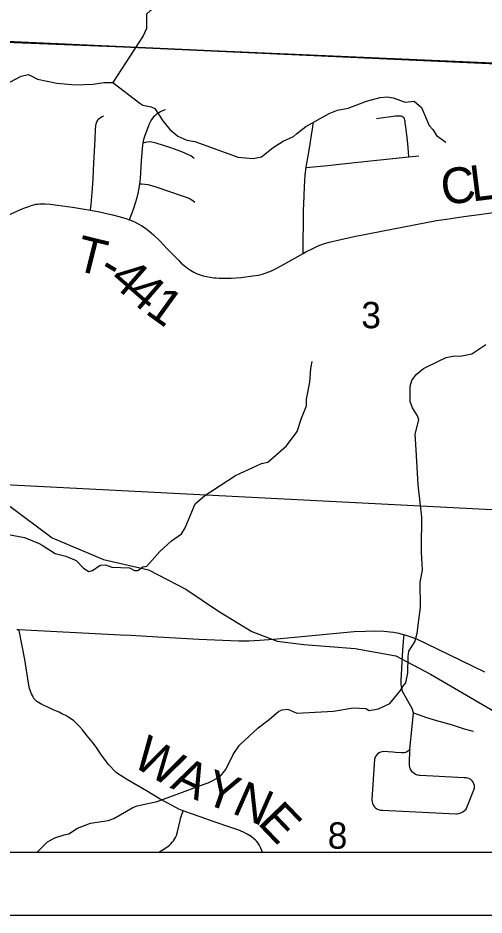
# Model space of a CAD drawing. Extents: x 0 to 34, y 0 to 22.
# Drawn here: x 2.723 to 3.463, y 14 to 15.425 of the extents above; entities that cross this region are included whole.
import ezdxf

# ---------------------------------------------------------------- set-up
doc = ezdxf.new("R2010")
doc.units = 0
for name, color, linetype in [('GM_X_County_Road', 7, 'Continuous'), ('GM_X_County_Road_Text', 7, 'Continuous'), ('GM_X_Minor_River', 7, 'Continuous'), ('GM_X_Rail_Line', 7, 'Continuous'), ('GM_X_Section', 7, 'Continuous'), ('GM_X_Section_Text', 7, 'Continuous'), ('GM_X_State_Route', 7, 'Continuous'), ('GM_X_Township_Road', 7, 'Continuous'), ('GM_X_Township_Road_Text', 7, 'Continuous'), ('GM_X_Unincorporated_Text', 7, 'Continuous'), ('SH_Data', 7, 'Continuous')]:
    doc.layers.add(name, color=color, linetype=linetype)

msp = doc.modelspace()

# ---------------------------------------------------------------- linework, layer by layer
at = {"layer": 'GM_X_County_Road'}
for points in [[(2.7863, 14.3229), (2.7788, 14.3262), (2.7699, 14.3301), (2.7606, 14.3344), (2.7579, 14.3359), (2.7552, 14.3374), (2.7525, 14.3393), (2.7504, 14.3413), (2.7479, 14.344), (2.7469, 14.3459), (2.7456, 14.3487), (2.7443, 14.3513), (2.7431, 14.3541), (2.7412, 14.3598), (2.7405, 14.3627), (2.7395, 14.3682), (2.7334, 14.4058), (2.725, 14.4495), (2.7243, 14.4533)], [(2.9851, 14.1655), (2.9837, 14.166), (2.978, 14.1683), (2.9676, 14.1738), (2.9486, 14.1843), (2.9269, 14.1972), (2.8967, 14.2149), (2.8866, 14.221), (2.8825, 14.2236), (2.8788, 14.2266), (2.8743, 14.2306), (2.87, 14.2352), (2.8661, 14.2396), (2.8607, 14.2468), (2.8571, 14.2517), (2.8535, 14.2572), (2.8474, 14.2659), (2.8403, 14.2752), (2.8327, 14.2847), (2.825, 14.294), (2.8204, 14.2994), (2.8159, 14.3041), (2.8115, 14.3084), (2.8063, 14.3124), (2.8021, 14.315), (2.7989, 14.3167), (2.7937, 14.3193), (2.7882, 14.3221), (2.7863, 14.3229)], [(3.1108, 14.1), (3.1085, 14.106), (3.1058, 14.1116), (3.1041, 14.1142), (3.1021, 14.1167), (3.0999, 14.119), (3.0969, 14.1216), (3.0928, 14.1246), (3.0866, 14.1286), (3.0807, 14.1314), (3.0734, 14.1346), (3.0593, 14.1396), (3.0342, 14.1483), (3.0135, 14.1554), (2.9968, 14.1611), (2.9851, 14.1655)]]:
    msp.add_lwpolyline(points, dxfattribs=at)
at = {"layer": 'GM_X_Minor_River'}
for points in [[(3.0044, 15.5355), (2.9817, 15.4934), (2.9603, 15.4728), (2.955, 15.4693), (2.9332, 15.4369), (2.9268, 15.4312), (2.927, 15.408), (2.9213, 15.3966), (2.8733, 15.3227)], [(2.6921, 15.3141), (2.728, 15.3325), (2.7389, 15.3352), (2.745, 15.3326), (2.7537, 15.3277), (2.7844, 15.3214), (2.8136, 15.3186), (2.8423, 15.3198), (2.8589, 15.3226), (2.8733, 15.3227), (2.9162, 15.2895), (2.9212, 15.2865), (2.9344, 15.2839), (2.9401, 15.2809), (2.9527, 15.2616)], [(2.9527, 15.2616), (2.9641, 15.2476), (2.9766, 15.2374), (2.9907, 15.2307), (3.0035, 15.2288), (3.0574, 15.2094), (3.0634, 15.2071), (3.0721, 15.2041), (3.0964, 15.2016), (3.1092, 15.2043), (3.128, 15.2192), (3.1439, 15.2292), (3.1601, 15.2365), (3.165, 15.2407), (3.1797, 15.2526), (3.2167, 15.2733), (3.2303, 15.2787), (3.2469, 15.2818), (3.2759, 15.2929), (3.2979, 15.2988), (3.3092, 15.2996), (3.3187, 15.2981), (3.3376, 15.2914), (3.352, 15.2926), (3.3634, 15.2828), (3.3756, 15.2544), (3.3813, 15.2476), (3.3871, 15.2385), (3.4023, 15.2279)], [(2.7531, 14.1), (2.7694, 14.1165), (2.7811, 14.1227), (2.7962, 14.1273), (2.8034, 14.1289), (2.8174, 14.1381), (2.8381, 14.1461), (2.8661, 14.1501), (2.8748, 14.1536), (2.9053, 14.1708), (2.9121, 14.1735), (2.9439, 14.1801), (3.0183, 14.2079), (3.025, 14.2102), (3.0435, 14.2194), (3.0526, 14.2312), (3.0642, 14.2552), (3.0747, 14.2697), (3.104, 14.2972), (3.1218, 14.3106), (3.1368, 14.3239), (3.1425, 14.3262), (3.1512, 14.3271), (3.1656, 14.3207), (3.2238, 14.3237), (3.2552, 14.3291), (3.2752, 14.3281), (3.2802, 14.3251), (3.2953, 14.3275), (3.313, 14.3359), (3.3303, 14.3569), (3.3337, 14.363), (3.3386, 14.3691), (3.3419, 14.3847), (3.3421, 14.4109), (3.3436, 14.4192), (3.353, 14.4341), (3.3567, 14.447), (3.3589, 14.4649), (3.3618, 14.4884), (3.3616, 14.529), (3.3649, 14.5477), (3.3636, 14.5765), (3.3636, 14.583), (3.3641, 14.632), (3.3582, 14.6836), (3.3552, 14.739), (3.3532, 14.7637), (3.3591, 14.7865), (3.3572, 14.7929), (3.3492, 14.8058), (3.3454, 14.8156), (3.3456, 14.8399), (3.3482, 14.8491), (3.355, 14.8586), (3.3667, 14.8682), (3.3916, 14.8804), (3.4025, 14.8854), (3.4161, 14.8882), (3.4248, 14.8878), (3.4433, 14.8917), (3.4656, 14.9063)], [(2.7989, 14.57), (2.8152, 14.5629), (2.827, 14.5508), (2.835, 14.5455), (2.841, 14.5475), (2.8531, 14.5555), (2.8618, 14.5563), (2.872, 14.5526), (2.9, 14.5516), (2.908, 14.5475), (2.9132, 14.5471), (2.9212, 14.5529), (2.9276, 14.5544), (2.9479, 14.5777), (2.9667, 14.5945), (2.9716, 14.5979), (2.9822, 14.6056), (2.9882, 14.6151), (3.0042, 14.6532), (3.0197, 14.6665), (3.0683, 14.6983), (3.1095, 14.7175), (3.1193, 14.7195), (3.149, 14.7455), (3.1663, 14.7683), (3.173, 14.7893), (3.1809, 14.809), (3.1808, 14.8193), (3.1863, 14.8463), (3.1877, 14.8683), (3.1899, 14.8793)], [(2.6992, 14.6063), (2.7333, 14.5997), (2.7564, 14.5903), (2.7614, 14.5873), (2.7818, 14.5741), (2.7989, 14.57)]]:
    msp.add_lwpolyline(points, dxfattribs=at)
at = {"layer": 'GM_X_Rail_Line'}
for points in [[(2.1, 18.4819), (2.1, 15.4153), (3.9123, 15.3323), (3.9451, 15.3313), (3.973, 15.329), (4.0133, 15.3262), (4.0257, 15.3251), (4.0381, 15.324), (4.0782, 15.3206), (4.1061, 15.3185), (4.1743, 15.3141), (4.1849, 15.3132), (4.1956, 15.3121), (4.1973, 15.3118), (5.1044, 15.2759), (5.2458, 15.271), (5.4522, 15.2638), (5.479, 15.731), (5.4821, 15.8189)], [(2.7058, 14.6525), (2.777, 14.599), (2.8584, 14.5647), (2.9302, 14.5482), (2.9894, 14.5175), (3.0412, 14.4829), (3.0941, 14.4502), (3.1342, 14.4352), (3.1768, 14.4296), (3.258, 14.4232), (3.3229, 14.4116), (3.3777, 14.3824), (3.5429, 14.2865)]]:
    msp.add_lwpolyline(points, dxfattribs=at)
msp.add_lwpolyline([(2.1, 15.4153), (2.1, 14.1), (6.4223, 14.1), (6.4607, 14.8895), (6.4764, 15.22), (6.2705, 15.2288), (5.4522, 15.2638), (5.2458, 15.271), (5.1044, 15.2759), (4.1973, 15.3118), (4.1956, 15.3121), (4.1849, 15.3132), (4.1743, 15.3141), (4.1061, 15.3185), (4.0782, 15.3206), (4.0381, 15.324), (4.0257, 15.3251), (4.0133, 15.3262), (3.973, 15.329), (3.9451, 15.3313), (3.9123, 15.3323)], close=True, dxfattribs=at)
at = {"layer": 'GM_X_Section'}
msp.add_lwpolyline([(2.9571, 15.3766), (3.7314, 15.3424), (3.7021, 14.6318), (2.6704, 14.6848), (2.7035, 15.3864)], close=True, dxfattribs=at)
at = {"layer": 'GM_X_State_Route'}
for points in [[(2.7211, 14.4534), (2.7243, 14.4533), (2.8855, 14.4452)], [(2.8855, 14.4452), (2.9015, 14.4444), (2.9449, 14.4418), (3.0098, 14.4381), (3.0736, 14.4356), (3.0895, 14.4356), (3.1062, 14.4364), (3.1286, 14.4381), (3.1617, 14.4413), (3.2567, 14.4502), (3.2747, 14.451), (3.2885, 14.4515), (3.3039, 14.451), (3.319, 14.4494), (3.3276, 14.4475), (3.3358, 14.4453), (3.3368, 14.4451), (3.3449, 14.4426), (3.3557, 14.4386), (3.3886, 14.423), (3.4633, 14.3863)]]:
    msp.add_lwpolyline(points, dxfattribs=at)
at = {"layer": 'GM_X_Township_Road'}
msp.add_line((3.3434, 15.2043), (3.359, 15.2059), dxfattribs=at)
for points in [[(2.9216, 15.2268), (2.9227, 15.2318), (2.9237, 15.2355), (2.9249, 15.2388), (2.9279, 15.2469), (2.9312, 15.2555), (2.9326, 15.2588), (2.9341, 15.2619), (2.9354, 15.2639), (2.9373, 15.2664), (2.9392, 15.2688), (2.9415, 15.2711), (2.9438, 15.273), (2.9462, 15.2747), (2.9493, 15.2765), (2.9529, 15.2781), (2.957, 15.2795)], [(2.838, 15.1195), (2.8389, 15.1284), (2.8402, 15.1415), (2.8411, 15.154), (2.842, 15.1696), (2.8432, 15.1946), (2.8451, 15.232), (2.8458, 15.2476), (2.8464, 15.2537), (2.847, 15.2568), (2.8479, 15.2598), (2.8493, 15.2625), (2.8513, 15.2649), (2.8536, 15.2669), (2.8563, 15.2685), (2.8592, 15.2695)], [(3.292, 15.2652), (3.3221, 15.2694), (3.3282, 15.2697), (3.3298, 15.2696), (3.3312, 15.2693), (3.3323, 15.269), (3.333, 15.2687), (3.3335, 15.2684), (3.3341, 15.268), (3.3347, 15.2674)], [(3.3434, 15.2043), (3.3425, 15.219), (3.3412, 15.2301), (3.3385, 15.2521), (3.3378, 15.2581), (3.3373, 15.2611), (3.3369, 15.2628), (3.3363, 15.2646), (3.336, 15.2655), (3.3357, 15.2661), (3.3353, 15.2668), (3.3347, 15.2674)], [(3.1803, 15.1873), (3.1808, 15.1909), (3.1833, 15.2061), (3.186, 15.2213), (3.1901, 15.2456), (3.1911, 15.2517), (3.1917, 15.2577)], [(2.9164, 15.1613), (2.9172, 15.1702), (2.9191, 15.1981), (2.9205, 15.2174), (2.921, 15.2226), (2.9216, 15.2268)], [(2.9216, 15.2268), (2.9251, 15.2277), (2.928, 15.2283), (2.9312, 15.2285), (2.9354, 15.2281), (2.9418, 15.2265), (2.9648, 15.219), (2.9823, 15.2128), (2.9943, 15.2078), (2.9974, 15.2063), (2.9999, 15.2045), (3.0025, 15.2021)], [(3.1803, 15.1873), (3.2148, 15.1907), (3.2382, 15.1932), (3.2722, 15.197), (3.2978, 15.1997), (3.3434, 15.2043)], [(3.1754, 15.0509), (3.1762, 15.1186), (3.177, 15.1425), (3.1776, 15.1573), (3.178, 15.1661), (3.1789, 15.1757), (3.1803, 15.1873)], [(2.8996, 15.1043), (2.9009, 15.1075), (2.9039, 15.1155), (2.9073, 15.1245), (2.9095, 15.1313), (2.9119, 15.1398), (2.9142, 15.1488), (2.9159, 15.1579), (2.9164, 15.1613)], [(2.9164, 15.1613), (2.9196, 15.1613), (2.924, 15.161), (2.9287, 15.1604), (2.9347, 15.1591), (2.9448, 15.1557), (2.9816, 15.1432), (2.9932, 15.139), (2.9964, 15.1375), (2.9987, 15.1363), (3.0011, 15.1344), (3.0035, 15.1324)], [(2.5577, 15.0512), (2.5773, 15.0578), (2.5878, 15.0617), (2.5976, 15.0656), (2.6721, 15.0956), (2.6861, 15.1016), (2.6982, 15.1073), (2.7259, 15.12), (2.732, 15.1227), (2.7399, 15.1257), (2.7452, 15.1275), (2.7478, 15.1282), (2.7509, 15.129), (2.754, 15.1294), (2.7569, 15.1296), (2.7593, 15.1296), (2.7659, 15.1295), (2.774, 15.129), (2.7856, 15.1276), (2.8092, 15.1244), (2.8317, 15.1207), (2.838, 15.1195)], [(3.1754, 15.0509), (3.1797, 15.0533), (3.1907, 15.059), (3.1993, 15.0629), (3.2081, 15.0662), (3.2171, 15.0689), (3.2352, 15.0733), (3.2566, 15.0776), (3.3002, 15.0864), (3.3873, 15.103), (3.403, 15.1051), (3.4306, 15.1094), (3.4552, 15.113), (3.486, 15.1172), (3.5015, 15.1188), (3.5201, 15.1201), (3.5543, 15.1218), (3.5729, 15.1225), (3.5885, 15.1224), (3.6017, 15.1219)], [(2.838, 15.1195), (2.8521, 15.117), (2.8729, 15.1124), (2.8849, 15.1092), (2.8939, 15.1065), (2.8996, 15.1043)], [(2.8996, 15.1043), (2.9039, 15.1026), (2.9088, 15.1005), (2.9137, 15.0981), (2.9192, 15.095), (2.9252, 15.0911), (2.9306, 15.087), (2.9379, 15.0804), (2.9478, 15.0709), (2.9598, 15.0584), (2.9779, 15.0396), (2.9821, 15.0354), (2.9864, 15.0316), (2.9917, 15.0277), (2.9966, 15.0242), (3.0019, 15.0213), (3.0073, 15.0187), (3.0122, 15.0169), (3.0168, 15.0154), (3.0222, 15.0142), (3.0278, 15.0132), (3.0337, 15.0124), (3.0377, 15.012), (3.0423, 15.0119), (3.0522, 15.0118), (3.0613, 15.0119), (3.0773, 15.0129), (3.0958, 15.0151), (3.1049, 15.0166), (3.1109, 15.018), (3.1168, 15.0199), (3.1253, 15.0234), (3.1337, 15.0274), (3.1446, 15.0333), (3.1754, 15.0509)], [(3.3449, 14.2633), (3.3448, 14.263), (3.3431, 14.2611), (3.3411, 14.2595), (3.3388, 14.2584), (3.3364, 14.2578), (3.3338, 14.2576), (3.3323, 14.2578), (3.3224, 14.2584), (3.3177, 14.2587), (3.3034, 14.2595), (3.3011, 14.2594), (3.2985, 14.2587), (3.296, 14.2576), (3.2938, 14.2561), (3.292, 14.2541), (3.2905, 14.2518), (3.2895, 14.2493), (3.2891, 14.2476), (3.2847, 14.1836), (3.2847, 14.1829), (3.2849, 14.1801), (3.2856, 14.1773), (3.2869, 14.1748), (3.2885, 14.1724), (3.2905, 14.1704), (3.2928, 14.1688), (3.2954, 14.1676), (3.2982, 14.1668), (3.301, 14.1666), (3.3017, 14.1666), (3.4178, 14.1608), (3.4192, 14.1609), (3.4226, 14.1614), (3.4259, 14.1624), (3.429, 14.1639), (3.4318, 14.1658), (3.4343, 14.1682), (3.4344, 14.1683), (3.4477, 14.2016), (3.4478, 14.2032), (3.4475, 14.2059), (3.4468, 14.2086), (3.4456, 14.211), (3.4439, 14.2132), (3.4419, 14.2151), (3.4395, 14.2165), (3.437, 14.2175), (3.4343, 14.218), (3.4315, 14.218), (3.4314, 14.218), (3.3616, 14.2214), (3.3598, 14.2215), (3.3569, 14.2221), (3.3541, 14.2233), (3.3516, 14.2248), (3.3494, 14.2267), (3.3476, 14.229), (3.3461, 14.2316), (3.3451, 14.2344), (3.3446, 14.2373), (3.3446, 14.2394), (3.3449, 14.2633), (3.3487, 14.2994), (3.351, 14.3211), (3.3487, 14.3279), (3.3333, 14.3552), (3.3328, 14.3581), (3.3322, 14.3598), (3.3316, 14.3628), (3.3314, 14.3662), (3.3312, 14.3724), (3.3322, 14.3911), (3.3335, 14.4129), (3.3349, 14.4347), (3.3354, 14.441), (3.3358, 14.4453)], [(3.351, 14.3211), (3.3564, 14.319), (3.358, 14.3183), (3.3713, 14.3139), (3.3872, 14.3092), (3.4106, 14.3024), (3.4314, 14.296), (3.4433, 14.2924), (3.4463, 14.2918)], [(2.9465, 14.1), (2.948, 14.1008), (2.956, 14.1057), (2.9611, 14.1092), (2.9635, 14.1112), (2.9657, 14.1133), (2.9678, 14.1156), (2.9697, 14.1181), (2.9714, 14.1207), (2.9729, 14.1234), (2.9742, 14.1262), (2.976, 14.1324), (2.9783, 14.1409), (2.9803, 14.15), (2.981, 14.1533), (2.9819, 14.1563), (2.9851, 14.1655)]]:
    msp.add_lwpolyline(points, dxfattribs=at)
at = {"layer": 'GM_X_Unincorporated_Text'}
msp.add_lwpolyline([(2.641, 14.1), (3.681, 14.1), (3.7021, 14.6318), (2.6704, 14.6848)], close=True, dxfattribs=at)
at = {"layer": 'SH_Data'}
for p, q in [((2.1, 14.1), (8.9, 14.1)), ((2, 14), (9, 14))]:
    msp.add_line(p, q, dxfattribs=at)

# ---------------------------------------------------------------- texts
at = {"layer": 'GM_X_County_Road_Text'}
for s, rotation, p in [('W', 329.4353, (2.9014, 14.2387)), ('A', 334.6648, (2.9631, 14.2026)), ('Y', 340.8412, (3.0145, 14.1787)), ('N', 336.1059, (3.0606, 14.1627)), ('E', 313.815, (3.1015, 14.1458))]:
    msp.add_text(s, height=0.0568, rotation=rotation, dxfattribs=at).set_placement(p)
at = {"layer": 'GM_X_Section_Text'}
for s, p in [('3', (3.2679, 14.9321)), ('8', (3.2146, 14.1054))]:
    msp.add_text(s, height=0.0419, rotation=0, dxfattribs=at).set_placement(p)
at = {"layer": 'GM_X_Township_Road_Text'}
for s, rotation, p in [('L', 7.0894, (3.4439, 15.1333)), ('C', 7.1531, (3.3976, 15.1275)), ('T', 346.1072, (2.8107, 15.0252)), ('-', 329.1407, (2.8479, 15.0167)), ('4', 318.9404, (2.8657, 15.0063)), ('4', 319.0554, (2.8922, 14.9832)), ('1', 324.3109, (2.9231, 14.9567))]:
    msp.add_text(s, height=0.0568, rotation=rotation, dxfattribs=at).set_placement(p)

doc.saveas('drawing.dxf')
